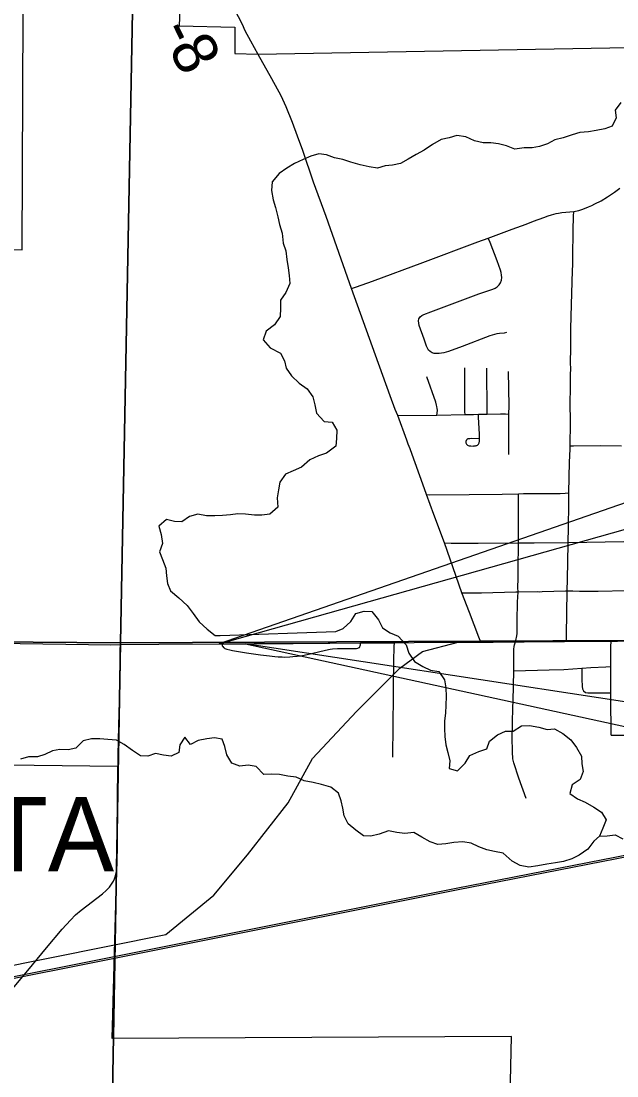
# Model space of a CAD drawing. Extents: x 0 to 42, y 0 to 22.
# Drawn here: x 5.107 to 5.866, y 16.928 to 18.271 of the extents above; entities that cross this region are included whole.
import ezdxf

# ---------------------------------------------------------------- set-up
doc = ezdxf.new("R2010")
doc.units = 0
for name, color, linetype in [('GM_X_City_Street', 7, 'Continuous'), ('GM_X_Corporation', 7, 'Continuous'), ('GM_X_Corporation_Text', 7, 'Continuous'), ('GM_X_County_Road', 7, 'Continuous'), ('GM_X_County_Road_Text', 7, 'Continuous'), ('GM_X_Minor_River', 7, 'Continuous'), ('GM_X_Rail_Line', 7, 'Continuous'), ('GM_X_Section', 7, 'Continuous'), ('GM_X_State_Route', 7, 'Continuous'), ('GM_X_US_Route', 7, 'Continuous'), ('SH_Text', 7, 'Continuous')]:
    doc.layers.add(name, color=color, linetype=linetype)

msp = doc.modelspace()

# ---------------------------------------------------------------- linework, layer by layer
at = {"layer": 'GM_X_City_Street'}
for points in [[(5.5278, 17.9312), (5.5338, 17.9331), (5.5544, 17.9404), (5.6186, 17.9643), (5.6887, 17.9904), (5.7019, 17.9951), (5.7324, 18.0064), (5.7501, 18.013), (5.7594, 18.0166), (5.7727, 18.0214), (5.7783, 18.0235), (5.7825, 18.0249), (5.7852, 18.0256), (5.7883, 18.0264), (5.7911, 18.027), (5.7956, 18.0277), (5.8006, 18.0283), (5.8107, 18.0292), (5.8128, 18.0296), (5.817, 18.0305), (5.8209, 18.0317), (5.8243, 18.0329), (5.8296, 18.0349), (5.8339, 18.0368), (5.8376, 18.0388), (5.8456, 18.0428), (5.8537, 18.0479), (5.8625, 18.0537), (5.8693, 18.0589)], [(5.8014, 17.482), (5.8016, 17.4895), (5.8024, 17.5459), (5.8027, 17.5608), (5.8036, 17.606), (5.8036, 17.6077), (5.8041, 17.6269), (5.8044, 17.6562), (5.8044, 17.6707), (5.8044, 17.6714), (5.8054, 17.7098), (5.806, 17.7265), (5.8061, 17.7306), (5.8064, 17.7602), (5.8065, 17.7626), (5.8063, 17.7843), (5.8064, 17.8055), (5.8065, 17.8208), (5.8069, 17.8297), (5.8067, 17.8353), (5.8072, 17.8565), (5.8072, 17.8798), (5.8079, 17.9108), (5.8091, 17.9533), (5.8091, 17.9562), (5.8094, 17.9589), (5.8097, 17.9708), (5.81, 18.0047), (5.8105, 18.0233), (5.8107, 18.0292)], [(5.7252, 17.8748), (5.7222, 17.8743), (5.716, 17.8737), (5.7128, 17.8732), (5.7098, 17.8724), (5.7038, 17.8706), (5.6687, 17.8572), (5.6511, 17.8509), (5.6452, 17.8493), (5.6391, 17.8483), (5.636, 17.8482), (5.6331, 17.8484), (5.6303, 17.8491), (5.6279, 17.8506), (5.6259, 17.8526), (5.6244, 17.8549), (5.6232, 17.8575), (5.6203, 17.8663), (5.6139, 17.8839), (5.6132, 17.8868), (5.613, 17.8897), (5.6136, 17.8925), (5.615, 17.8948), (5.6172, 17.8966), (5.6199, 17.898), (5.6286, 17.9011), (5.6899, 17.924), (5.7075, 17.9303), (5.7105, 17.9316), (5.7133, 17.9333), (5.7156, 17.9356), (5.7174, 17.9384), (5.7186, 17.9416), (5.719, 17.9448), (5.7188, 17.9481), (5.7182, 17.9513), (5.7173, 17.9543), (5.7131, 17.9662), (5.7042, 17.9895), (5.7019, 17.9951)], [(5.6722, 17.7704), (5.6721, 17.774), (5.6718, 17.83)], [(5.7004, 17.771), (5.7004, 17.7737), (5.7, 17.8295)], [(5.7281, 17.7712), (5.7283, 17.7818), (5.7278, 17.8253)], [(5.6364, 17.7699), (5.6367, 17.7721), (5.637, 17.776), (5.6369, 17.7782), (5.6365, 17.7808), (5.636, 17.7825), (5.635, 17.7861), (5.6234, 17.8185)], [(5.5866, 17.7693), (5.6364, 17.7699), (5.6722, 17.7704), (5.6832, 17.7706), (5.6894, 17.7708), (5.7004, 17.771), (5.7175, 17.7714), (5.7237, 17.7713), (5.7281, 17.7712)], [(5.6899, 17.7398), (5.6801, 17.7399), (5.6783, 17.7398), (5.6774, 17.7397), (5.6764, 17.7396), (5.6757, 17.7394), (5.675, 17.7391), (5.6744, 17.7385), (5.6738, 17.7379), (5.6735, 17.7373), (5.6733, 17.7364), (5.6731, 17.7354), (5.6732, 17.7346), (5.6735, 17.7335), (5.6739, 17.7329), (5.6744, 17.7322), (5.6752, 17.7316), (5.6763, 17.7311), (5.6777, 17.7308), (5.6797, 17.7305), (5.6825, 17.7304), (5.6836, 17.7305), (5.6847, 17.7305), (5.6855, 17.7307), (5.6863, 17.7309), (5.6873, 17.7312), (5.6881, 17.7317), (5.6888, 17.7322), (5.6893, 17.7328), (5.6897, 17.7335), (5.6901, 17.7344), (5.6903, 17.7352), (5.6905, 17.7362), (5.6905, 17.7457), (5.6895, 17.7673), (5.6894, 17.7708)], [(5.7282, 17.7198), (5.7281, 17.7694), (5.7281, 17.7712)], [(5.8061, 17.7306), (5.8105, 17.7306), (5.8444, 17.7311), (5.8716, 17.7307)], [(5.6233, 17.6687), (5.627, 17.6685), (5.6775, 17.6688), (5.7197, 17.6693), (5.7405, 17.6696), (5.7467, 17.6699), (5.7691, 17.6702), (5.7936, 17.6702), (5.7996, 17.6705), (5.8044, 17.6707)], [(5.7499, 17.2817), (5.7407, 17.3076), (5.7345, 17.3269), (5.7332, 17.3321), (5.7327, 17.341), (5.7328, 17.3442), (5.7323, 17.3566), (5.7326, 17.3783), (5.7331, 17.3969), (5.7335, 17.4062), (5.7342, 17.4443), (5.7344, 17.472), (5.7347, 17.475), (5.7353, 17.4775), (5.7365, 17.4811), (5.7374, 17.4848), (5.738, 17.4867), (5.7386, 17.4914), (5.7385, 17.5073), (5.7392, 17.532), (5.7396, 17.5382), (5.7398, 17.545), (5.7396, 17.55), (5.7398, 17.562), (5.7401, 17.5733), (5.7403, 17.6071), (5.7405, 17.6696)], [(5.6459, 17.6071), (5.6546, 17.6068), (5.6671, 17.6069), (5.6888, 17.6068), (5.7403, 17.6071), (5.7601, 17.607), (5.8036, 17.6077), (5.8747, 17.6088)], [(5.6683, 17.5436), (5.675, 17.5436), (5.6934, 17.5437), (5.7369, 17.545), (5.7398, 17.545), (5.7644, 17.5451), (5.7672, 17.545), (5.7704, 17.5453), (5.8002, 17.5459), (5.8024, 17.5459), (5.8097, 17.546), (5.8181, 17.5458), (5.8269, 17.5457), (5.842, 17.5458), (5.878, 17.5467)], [(5.3625, 17.4787), (5.3627, 17.4772), (5.3631, 17.4761), (5.3637, 17.475), (5.3647, 17.4739), (5.3655, 17.4733), (5.3665, 17.4728), (5.3677, 17.4722), (5.369, 17.4718), (5.3727, 17.4708), (5.376, 17.4702), (5.394, 17.4672), (5.4119, 17.4647), (5.4232, 17.4632), (5.4302, 17.4625), (5.4341, 17.4622), (5.4377, 17.4619), (5.4395, 17.4619), (5.4427, 17.4618), (5.449, 17.462), (5.4528, 17.4623), (5.4583, 17.4628), (5.4626, 17.4634), (5.4675, 17.4642), (5.4766, 17.4661), (5.4945, 17.4707), (5.5005, 17.4719), (5.5035, 17.4722), (5.5096, 17.4726), (5.5219, 17.4725), (5.5313, 17.4727), (5.5341, 17.4728), (5.5355, 17.473), (5.5366, 17.4734), (5.5377, 17.4741), (5.5384, 17.4752), (5.5387, 17.4759), (5.539, 17.4771), (5.5391, 17.4782), (5.5393, 17.4798)], [(5.5802, 17.3342), (5.5809, 17.3749), (5.5813, 17.4125), (5.5812, 17.4251), (5.5817, 17.4564), (5.5821, 17.4752), (5.5822, 17.48)], [(5.8583, 17.3621), (5.8581, 17.4113), (5.858, 17.416), (5.8579, 17.4238), (5.858, 17.4426), (5.8581, 17.4496), (5.8581, 17.4551), (5.8579, 17.4708), (5.858, 17.474), (5.8582, 17.4828)], [(5.7342, 17.4443), (5.7793, 17.4453), (5.7981, 17.4461), (5.8209, 17.4478), (5.821, 17.4429), (5.8212, 17.4337), (5.8214, 17.4244), (5.822, 17.4214), (5.8232, 17.4186), (5.8255, 17.4167), (5.8285, 17.4162), (5.8347, 17.4162), (5.8531, 17.416), (5.858, 17.416)], [(5.8209, 17.4478), (5.8326, 17.4486), (5.8515, 17.4494), (5.8581, 17.4496)], [(5.8583, 17.3621), (5.8862, 17.3621), (5.9051, 17.3619), (5.94, 17.3623), (5.9785, 17.3625), (5.9847, 17.3623), (5.9876, 17.3619), (5.991, 17.3612), (5.9935, 17.3604), (6.02, 17.3513), (6.0331, 17.3467), (6.0522, 17.3402), (6.0717, 17.3333), (6.0859, 17.3281), (6.1125, 17.3189), (6.1186, 17.3174), (6.1217, 17.3169), (6.124, 17.3167), (6.128, 17.3165), (6.153, 17.3163), (6.1872, 17.3163), (6.1996, 17.3165), (6.2044, 17.3166)]]:
    msp.add_lwpolyline(points, dxfattribs=at)
at = {"layer": 'GM_X_Corporation'}
for points in [[(5.056, 17.982), (5.1081, 17.9802), (5.1104, 18.482)], [(5.3129, 18.3855), (5.308, 18.2653), (5.3792, 18.2639), (5.3792, 18.2301), (5.4084, 18.2295), (5.951, 18.2391), (6.2578, 18.2418), (6.26, 18.3342)], [(7.4791, 16.966), (6.494, 16.9822), (6.296, 16.9865), (5.9668, 16.9849), (5.9629, 16.9596), (5.9548, 16.9192), (5.9428, 16.8603), (5.9405, 16.8458), (5.9389, 16.8325), (5.9381, 16.82), (5.9379, 16.8075), (5.9391, 16.7888), (5.9408, 16.7765), (5.9441, 16.7612), (5.7267, 16.7683), (5.7313, 16.9785), (5.223, 16.9761), (5.2286, 17.1938), (5.2302, 17.3226), (4.7322, 17.3283)]]:
    msp.add_lwpolyline(points, dxfattribs=at)
at = {"layer": 'GM_X_County_Road'}
msp.add_line((5.6683, 17.5436), (5.6459, 17.6071), dxfattribs=at)
for points in [[(5.4086, 18.2289), (5.3993, 18.2459), (5.3924, 18.2592), (5.3886, 18.2673), (5.3785, 18.2865), (5.3758, 18.2922), (5.3736, 18.2981), (5.3719, 18.3042), (5.3699, 18.3133), (5.3685, 18.3226), (5.3679, 18.332), (5.3667, 18.3567), (5.3659, 18.3852)], [(5.5278, 17.9312), (5.5225, 17.9454), (5.4952, 18.0228), (5.4794, 18.0665), (5.4656, 18.1068), (5.459, 18.1251), (5.4525, 18.1424), (5.4444, 18.1622), (5.4379, 18.1762), (5.4262, 18.1981), (5.4086, 18.2289)], [(5.5866, 17.7693), (5.5832, 17.777), (5.577, 17.7943), (5.5583, 17.8463), (5.5278, 17.9312)], [(5.6233, 17.6687), (5.6184, 17.6818), (5.6048, 17.7198), (5.6022, 17.7268), (5.5999, 17.7329), (5.5981, 17.7377), (5.5866, 17.7693)], [(5.6459, 17.6071), (5.6323, 17.6434), (5.6233, 17.6687)], [(5.6923, 17.4807), (5.6899, 17.487), (5.6781, 17.5183), (5.6683, 17.5436)], [(5.2304, 17.322), (5.2306, 17.337), (5.2315, 17.3743), (5.2322, 17.4054), (5.2329, 17.4582), (5.2332, 17.4707), (5.2334, 17.4776)], [(5.2288, 17.1932), (5.2291, 17.1971), (5.2295, 17.2251), (5.2304, 17.322)], [(5.0896, 17.0315), (5.1153, 17.0627), (5.139, 17.0916), (5.1591, 17.1154), (5.1696, 17.1269), (5.1763, 17.1334), (5.1835, 17.1395), (5.2106, 17.1604), (5.2152, 17.1645), (5.2194, 17.1689), (5.2213, 17.1713), (5.223, 17.1738), (5.2245, 17.1764), (5.2258, 17.1792), (5.2268, 17.182), (5.2276, 17.185), (5.2286, 17.191), (5.2288, 17.1932)]]:
    msp.add_lwpolyline(points, dxfattribs=at)
at = {"layer": 'GM_X_Minor_River'}
for points in [[(5.8706, 18.1678), (5.8635, 18.1581), (5.8648, 18.1482), (5.8596, 18.1376), (5.8501, 18.1344), (5.8394, 18.132), (5.8295, 18.1303), (5.8184, 18.1295), (5.8085, 18.1266), (5.7974, 18.1227), (5.7867, 18.1203), (5.7771, 18.1152), (5.7672, 18.112), (5.7577, 18.1099), (5.7474, 18.1102), (5.7356, 18.1085), (5.7251, 18.1126), (5.7149, 18.1154)], [(5.7149, 18.1154), (5.7051, 18.1164), (5.6952, 18.1163), (5.6843, 18.1192), (5.6734, 18.124), (5.6617, 18.1257), (5.6521, 18.1229), (5.6418, 18.1205), (5.631, 18.1143), (5.6202, 18.1073), (5.6102, 18.1015), (5.5999, 18.0956), (5.5899, 18.0902), (5.58, 18.0881), (5.5705, 18.0872), (5.5609, 18.0844), (5.5503, 18.0857), (5.5386, 18.0883), (5.5269, 18.0919), (5.5168, 18.0952), (5.5058, 18.0973), (5.496, 18.101), (5.4862, 18.1023), (5.4759, 18.0995), (5.4659, 18.0952), (5.4552, 18.0901), (5.4452, 18.0843), (5.4355, 18.0773), (5.4266, 18.0669), (5.4259, 18.0559), (5.4279, 18.0437), (5.4307, 18.0341), (5.4339, 18.0223), (5.4359, 18.0124), (5.4394, 18.0013), (5.4407, 17.9887), (5.4438, 17.9788), (5.4451, 17.9681), (5.4468, 17.9575), (5.4484, 17.9476), (5.4489, 17.9373), (5.4441, 17.926), (5.4371, 17.9163), (5.4372, 17.9061), (5.4366, 17.8954), (5.4295, 17.8846), (5.419, 17.8765), (5.415, 17.8656), (5.4239, 17.8555), (5.4374, 17.8487), (5.4421, 17.8391), (5.4445, 17.8296), (5.4511, 17.82), (5.4611, 17.8106), (5.4712, 17.8032), (5.4786, 17.7932), (5.481, 17.7829), (5.483, 17.7722), (5.493, 17.7617), (5.5028, 17.7607), (5.5091, 17.7507), (5.5084, 17.7401), (5.5078, 17.7303), (5.4958, 17.7214), (5.4855, 17.7178), (5.4744, 17.7128), (5.4639, 17.7035), (5.4532, 17.6988), (5.4436, 17.6945), (5.4365, 17.6844), (5.4348, 17.6746), (5.433, 17.6644), (5.4339, 17.6526), (5.4235, 17.6437), (5.4136, 17.6424), (5.4041, 17.6426), (5.3927, 17.6436), (5.3829, 17.6442), (5.3734, 17.6429), (5.3635, 17.642), (5.3536, 17.6415), (5.343, 17.6417), (5.332, 17.6435), (5.3213, 17.6407), (5.3117, 17.634), (5.3022, 17.6343), (5.292, 17.6368), (5.2823, 17.6286), (5.2851, 17.6176), (5.2868, 17.6065), (5.2831, 17.5956), (5.287, 17.586), (5.2913, 17.5749), (5.2919, 17.565), (5.2932, 17.5555), (5.2971, 17.5459), (5.3079, 17.537), (5.3183, 17.5272), (5.326, 17.5172), (5.3337, 17.5064), (5.3438, 17.4971)], [(5.5076, 17.4942), (5.5172, 17.4981), (5.5269, 17.507), (5.5332, 17.5171), (5.5439, 17.5203), (5.5537, 17.5197), (5.5622, 17.5093), (5.5673, 17.4989), (5.577, 17.4926), (5.5871, 17.4882), (5.5971, 17.4774), (5.6007, 17.4667), (5.608, 17.4559), (5.6185, 17.4496), (5.6282, 17.4452), (5.6388, 17.4434), (5.6462, 17.4326), (5.6478, 17.4227), (5.6483, 17.4117), (5.6477, 17.4003), (5.6474, 17.3905), (5.6461, 17.3806), (5.6462, 17.3707), (5.6467, 17.3605), (5.6476, 17.3502), (5.6505, 17.3403), (5.6529, 17.3296), (5.6519, 17.3198), (5.6628, 17.3169), (5.6725, 17.3265), (5.6784, 17.3366), (5.6899, 17.3417), (5.6999, 17.3449), (5.7035, 17.3547), (5.7136, 17.3628), (5.7239, 17.3675), (5.7334, 17.3673), (5.7442, 17.3742), (5.7544, 17.3744), (5.7662, 17.3726), (5.7767, 17.3697), (5.7862, 17.3703), (5.7967, 17.3643), (5.8068, 17.3565), (5.8141, 17.3465), (5.8207, 17.3357), (5.8208, 17.3258), (5.8229, 17.3159), (5.8189, 17.3058), (5.8088, 17.2992), (5.8059, 17.2882), (5.8156, 17.2812), (5.8254, 17.2768), (5.8363, 17.2708), (5.846, 17.2642), (5.8518, 17.2546), (5.8478, 17.244), (5.8437, 17.2339), (5.8532, 17.234), (5.8635, 17.2353), (5.8732, 17.2302)], [(5.3438, 17.4971), (5.3542, 17.4892), (5.3603, 17.4891)], [(5.3603, 17.4891), (5.5076, 17.4942)], [(5.8437, 17.2339), (5.8364, 17.2272), (5.8286, 17.2171), (5.8177, 17.2094), (5.8082, 17.2047), (5.7975, 17.2015), (5.7876, 17.1998), (5.7765, 17.1982), (5.7651, 17.1958), (5.7533, 17.1941), (5.7423, 17.1963), (5.7322, 17.2018), (5.7207, 17.2119), (5.7097, 17.2141), (5.6999, 17.2162), (5.6898, 17.2202), (5.68, 17.225), (5.6694, 17.2264), (5.658, 17.2255), (5.6477, 17.2238), (5.6378, 17.2229), (5.6277, 17.2265), (5.6172, 17.2325), (5.6071, 17.2384), (5.5957, 17.2371), (5.5855, 17.2385), (5.5749, 17.2406), (5.563, 17.2363), (5.5524, 17.2339), (5.5429, 17.2341), (5.5332, 17.2412), (5.5235, 17.2494), (5.5181, 17.2597), (5.5164, 17.2693), (5.5143, 17.2788), (5.5111, 17.2884), (5.5015, 17.2962), (5.4894, 17.2995), (5.4788, 17.302), (5.4675, 17.3041), (5.457, 17.3089), (5.4464, 17.3103), (5.4358, 17.3121), (5.4256, 17.3127), (5.4161, 17.3121), (5.4061, 17.3222), (5.3959, 17.324), (5.3856, 17.3227), (5.3754, 17.3267), (5.3689, 17.3371), (5.3661, 17.3478), (5.3629, 17.3573), (5.3531, 17.3587), (5.3432, 17.3578), (5.3325, 17.3554), (5.3225, 17.3503), (5.3155, 17.3599), (5.3092, 17.3502), (5.3079, 17.3404), (5.2979, 17.3356), (5.288, 17.337), (5.2779, 17.3391), (5.2683, 17.3355), (5.2588, 17.3358), (5.2487, 17.3428), (5.2383, 17.3506), (5.2285, 17.3558), (5.2172, 17.3568), (5.207, 17.3578), (5.1963, 17.3576), (5.1857, 17.3552), (5.1767, 17.3456), (5.1668, 17.3435), (5.1562, 17.3441), (5.1467, 17.3424), (5.1371, 17.3377), (5.1275, 17.3345), (5.1161, 17.3348), (5.1062, 17.3316)]]:
    msp.add_lwpolyline(points, dxfattribs=at)
at = {"layer": 'GM_X_Rail_Line'}
for points in [[(4.4738, 16.9443), (5.2911, 17.1083), (5.3521, 17.1586), (5.3953, 17.2101), (5.4468, 17.276), (5.4779, 17.3324), (5.5342, 17.3923), (5.5893, 17.4474), (5.618, 17.4689), (5.6635, 17.4809), (6.1368, 17.4838), (6.5418, 17.4827), (6.748, 17.4796), (7.1583, 17.4796), (7.645, 17.5773), (8.6737, 17.7802), (8.9, 17.8248)], [(2.1, 16.459), (2.2129, 16.4808), (2.5454, 16.5465), (3.2154, 16.6797), (3.8608, 16.8081), (4.4734, 16.9293), (4.9678, 17.0293), (5.6609, 17.1675), (6.33, 17.2984), (6.9548, 17.4275), (7.5722, 17.5495), (8.2054, 17.6814), (8.8625, 17.8098), (8.9, 17.8172)], [(2.1, 16.4567), (2.2123, 16.4784), (2.5452, 16.5433), (3.215, 16.6775), (3.8612, 16.8058), (4.4739, 16.927), (4.9682, 17.0271), (5.6614, 17.1653), (6.3305, 17.2961), (6.9553, 17.4252), (7.5727, 17.5472), (8.2058, 17.6791), (8.8629, 17.8076), (8.9, 17.8149)]]:
    msp.add_lwpolyline(points, dxfattribs=at)
at = {"layer": 'GM_X_Section'}
for points in [[(4.2501, 18.4923), (5.2524, 18.4847), (5.2334, 17.4797), (4.2338, 17.4876)], [(5.2524, 18.4847), (6.2631, 18.4885), (6.2427, 17.4846), (5.2334, 17.4797)], [(5.2334, 17.4797), (5.2156, 16.4769), (4.2153, 16.4855), (4.2338, 17.4876)], [(6.2427, 17.4846), (6.224, 16.494), (5.6923, 16.4799), (5.2156, 16.4769), (5.2334, 17.4797)]]:
    msp.add_lwpolyline(points, close=True, dxfattribs=at)
at = {"layer": 'GM_X_State_Route'}
for p, q in [((5.5393, 17.4798), (5.5822, 17.48)), ((5.5822, 17.48), (5.6074, 17.4802)), ((5.8582, 17.4828), (5.8621, 17.4829)), ((5.8621, 17.4829), (5.8784, 17.4831))]:
    msp.add_line(p, q, dxfattribs=at)
for points in [[(5.0448, 17.4797), (5.0465, 17.4797), (5.1055, 17.4791), (5.1925, 17.4778), (5.2204, 17.4775), (5.2334, 17.4776)], [(5.2334, 17.4776), (5.2823, 17.4781), (5.3625, 17.4787)], [(5.3625, 17.4787), (5.4036, 17.4788), (5.4533, 17.4791), (5.4979, 17.4794)], [(5.4979, 17.4794), (5.4999, 17.4794), (5.5393, 17.4798)], [(5.6074, 17.4802), (5.6487, 17.4805), (5.677, 17.4807), (5.6923, 17.4807)], [(5.6923, 17.4807), (5.708, 17.4807), (5.7297, 17.481), (5.7365, 17.4811)], [(5.7365, 17.4811), (5.7474, 17.4813), (5.8014, 17.482)], [(5.8014, 17.482), (5.8074, 17.4821), (5.826, 17.4823), (5.8582, 17.4828)]]:
    msp.add_lwpolyline(points, dxfattribs=at)
at = {"layer": 'GM_X_US_Route'}
for p, q in [((5.5393, 17.4798), (5.5822, 17.48)), ((5.5822, 17.48), (5.6074, 17.4802)), ((5.8582, 17.4828), (5.8621, 17.4829)), ((5.8621, 17.4829), (5.8784, 17.4831))]:
    msp.add_line(p, q, dxfattribs=at)
for points in [[(5.0448, 17.4797), (5.0465, 17.4797), (5.1055, 17.4791), (5.1925, 17.4778), (5.2204, 17.4775), (5.2334, 17.4776)], [(5.2334, 17.4776), (5.2823, 17.4781), (5.3625, 17.4787)], [(5.3625, 17.4787), (5.4036, 17.4788), (5.4533, 17.4791), (5.4979, 17.4794)], [(5.4979, 17.4794), (5.4999, 17.4794), (5.5393, 17.4798)], [(5.6074, 17.4802), (5.6487, 17.4805), (5.677, 17.4807), (5.6923, 17.4807)], [(5.6923, 17.4807), (5.708, 17.4807), (5.7297, 17.481), (5.7365, 17.4811)], [(5.7365, 17.4811), (5.7474, 17.4813), (5.8014, 17.482)], [(5.8014, 17.482), (5.8074, 17.4821), (5.826, 17.4823), (5.8582, 17.4828)]]:
    msp.add_lwpolyline(points, dxfattribs=at)
at = {"layer": 'SH_Text'}
msp.add_line((5.359, 17.4787), (5.3926, 17.4787), dxfattribs=at)
for points in [[(9.439, 18.8951), (5.359, 17.4787), (9.439, 18.63)], [(9.439, 16.8599), (5.3926, 17.4787), (9.439, 16.5971)]]:
    msp.add_lwpolyline(points, close=True, dxfattribs=at)

# ---------------------------------------------------------------- texts
at = {"layer": 'GM_X_Corporation_Text'}
msp.add_text('DELTA', height=0.0947, rotation=0, dxfattribs=at).set_placement((4.8172, 17.1888))
at = {"layer": 'GM_X_County_Road_Text'}
for s, rotation, p in [('-', 295.6686, (5.2824, 18.2597)), ('8', 298.2196, (5.2938, 18.2362))]:
    msp.add_text(s, height=0.0568, rotation=rotation, dxfattribs=at).set_placement(p)

doc.saveas('drawing.dxf')
